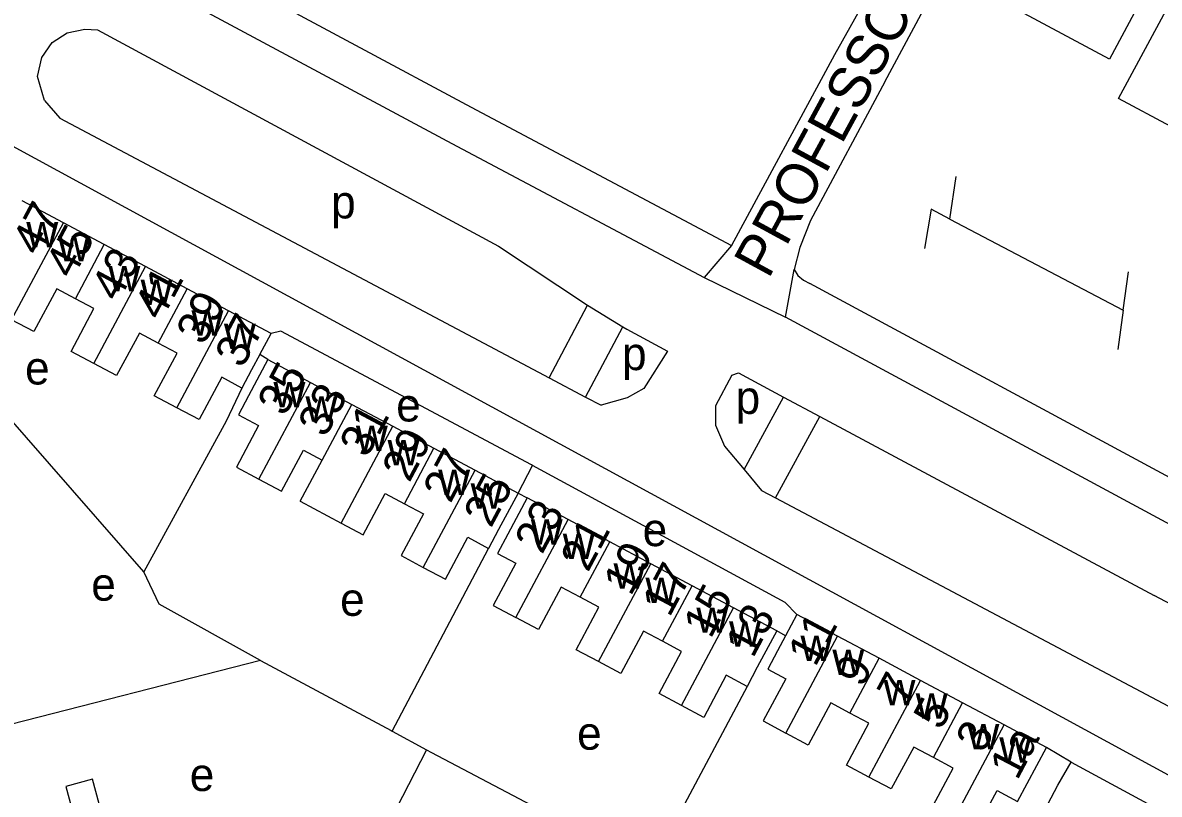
# Model space of a CAD drawing. Extents: x 159261 to 160849, y 382514 to 384534.
# Drawn here: x 159830 to 159967.8, y 383889.9 to 383983.5 of the extents above; entities that cross this region are included whole.
import ezdxf

# ---------------------------------------------------------------- set-up
doc = ezdxf.new("R2010")
doc.units = 0
for name, color, linetype in [('BLT_Basislijn', 7, 'Continuous'), ('BLT_Bebouwing', 7, 'Continuous'), ('BLT_Centroide', 7, 'Continuous'), ('BLT_Huisnummer', 7, 'Continuous'), ('BLT_Huisnummer_ tussenligend', 7, 'Continuous'), ('BLT_Onderverdeling_panden', 7, 'Continuous'), ('BLT_Straatnaam', 7, 'Continuous'), ('BLT_Vlakafsluiter', 7, 'Continuous')]:
    doc.layers.add(name, color=color, linetype=linetype)

msp = doc.modelspace()

# ---------------------------------------------------------------- linework, layer by layer
at = {"layer": 'BLT_Basislijn'}
for p, q in [((159839.08, 383982.65), (159887.72, 383956.4)), ((159934.58, 383976.36), (159925.54, 383959.53)), ((159832.65, 383974.09), (159834.49, 383971.94)), ((159834.49, 383971.94), (159893.84, 383940.44)), ((159942.45, 383959.68), (159943.21, 383964.85)), ((159942.45, 383959.68), (159963.45, 383948.63)), ((159887.72, 383956.4), (159898.51, 383949.24)), ((159915.98, 383956.49), (159912.64, 383952.6)), ((159963.45, 383948.63), (159964.13, 383953.27)), ((159893.84, 383940.44), (159898.51, 383949.24)), ((159963.45, 383948.63), (159962.81, 383943.87)), ((159898.25, 383938.09), (159902.78, 383946.63)), ((159908.2, 383943.68), (159905.32, 383939.15)), ((159859.73, 383942.63), (159858.76, 383943.25)), ((159916.01, 383940.76), (159914.02, 383937.04)), ((159893.84, 383940.44), (159898.25, 383938.09)), ((159898.25, 383938.09), (159900.14, 383937.09)), ((159917.49, 383929.28), (159922.27, 383938.09)), ((159921.32, 383925.85), (159926.68, 383935.73)), ((159890.08, 383926.42), (159891.85, 383929.8)), ((159890.08, 383926.42), (159891.19, 383925.88)), ((159919.59, 383926.76), (159921.32, 383925.85)), ((159921.32, 383925.85), (160059.63, 383852.41)), ((159874.82, 383897.54), (159886.5, 383919.73)), ((159970.74, 383912.14), (159967.23, 383914.01)), ((159922.53, 383909.11), (159921.45, 383909.72)), ((159858.86, 383906.11), (159823.8, 383897.17)), ((159917.85, 383902.98), (159908.67, 383885.71)), ((159874.82, 383897.54), (159878.99, 383895.29)), ((159878.99, 383895.29), (159867.87, 383873.72)), ((159957.15, 383893.79), (159954.15, 383895.56)), ((159957.15, 383893.79), (159967.4, 383888.25))]:
    msp.add_line(p, q, dxfattribs=at)
for points in [[(159957.87, 384042.43), (159958.71, 384041.58), (159959.45, 384040.29), (159959.85, 384038.79), (159959.81, 384037.11), (159936.09, 383993.31), (159928.44, 383979.64)], [(159934.58, 383976.36), (159962.75, 384028.88), (159963.83, 384030.2), (159964.72, 384031.01), (159965.91, 384031.42), (159967.49, 384031.39), (159970.07, 384030.28)], [(159809.86, 384007.63), (159882.05, 383968.86), (159912.64, 383952.6)], [(159842.32, 383995.87), (159884.41, 383973.27), (159915.98, 383956.49)], [(159832.65, 383974.09), (159831.79, 383976.99), (159832.31, 383979.3), (159833.59, 383981.1), (159835.38, 383982.3), (159837.52, 383982.72), (159839.08, 383982.65)], [(159928.44, 383979.64), (159915.98, 383956.49)], [(159823.19, 383971.58), (160049.97, 383848.1), (160067.5, 383838.6), (160083.66, 383829.43)], [(159942.45, 383959.68), (159940.17, 383960.89), (159939.39, 383956.12)], [(159925.54, 383959.53), (159924.26, 383956.25), (159923.58, 383953.58)], [(159922.51, 383947.79), (159923.58, 383953.58)], [(159923.58, 383953.58), (159924.02, 383952.85), (159924.7, 383952.29), (159925.48, 383951.86)], [(159971.17, 383927.2), (159925.48, 383951.86)], [(159898.51, 383949.24), (159902.78, 383946.63)], [(160121.72, 383847.78), (160116.87, 383847.25), (160111.62, 383847.44), (160105.79, 383849.21), (159987.63, 383912.63), (159922.51, 383947.79)], [(159902.78, 383946.63), (159903.27, 383946.33), (159908.2, 383943.68)], [(159891.85, 383929.8), (159891.7, 383929.88), (159861.3, 383946.09), (159860.12, 383945.8)], [(159844.68, 383916.88), (159821.76, 383943.08), (159811.97, 383941.18)], [(159916.01, 383940.76), (159916.8, 383941.03), (159922.27, 383938.09)], [(159856.59, 383939.19), (159854.69, 383935.16), (159844.68, 383916.88)], [(159905.32, 383939.15), (159903.32, 383937.99), (159900.14, 383937.09)], [(159922.27, 383938.09), (159926.68, 383935.73)], [(159914.02, 383937.04), (159914.02, 383934.68), (159915.11, 383932.14), (159917.49, 383929.28)], [(159926.68, 383935.73), (159967.23, 383914.01)], [(159923.91, 383911.71), (159922.47, 383913.16), (159891.85, 383929.8)], [(159917.49, 383929.28), (159919.59, 383926.76)], [(159858.86, 383906.11), (159846.57, 383912.97), (159844.68, 383916.88)], [(159858.86, 383906.11), (159874.7, 383897.61), (159874.82, 383897.54)], [(159878.99, 383895.29), (159879.59, 383894.97), (159906.08, 383881)], [(159943.21, 383867.55), (159955.54, 383890.99), (159957.15, 383893.79)]]:
    msp.add_lwpolyline(points, dxfattribs=at)
at = {"layer": 'BLT_Bebouwing'}
for p, q in [((159834.94, 383959.25), (159829.95, 383961.91)), ((159839.9, 383956.6), (159834.94, 383959.25)), ((159844.91, 383953.92), (159839.9, 383956.6)), ((159849.95, 383951.23), (159844.91, 383953.92)), ((159854.97, 383948.55), (159849.95, 383951.23)), ((159860.12, 383945.8), (159854.97, 383948.55)), ((159858.76, 383943.25), (159860.12, 383945.8)), ((159859.73, 383942.63), (159864.92, 383939.86)), ((159864.92, 383939.86), (159869.93, 383937.18)), ((159869.93, 383937.18), (159874.88, 383934.54)), ((159874.88, 383934.54), (159879.88, 383931.87)), ((159879.88, 383931.87), (159884.88, 383929.2)), ((159863.66, 383925.44), (159866.34, 383930.42)), ((159884.88, 383929.2), (159890.08, 383926.42)), ((159896.17, 383923.22), (159891.19, 383925.88)), ((159901.19, 383920.53), (159896.17, 383923.22)), ((159906.19, 383917.86), (159901.19, 383920.53)), ((159911.21, 383915.18), (159906.19, 383917.86)), ((159916.22, 383912.51), (159911.21, 383915.18)), ((159921.45, 383909.72), (159916.22, 383912.51)), ((159923.91, 383911.71), (159922.53, 383909.11)), ((159928.83, 383909.08), (159923.91, 383911.71)), ((159933.87, 383906.39), (159928.83, 383909.08)), ((159938.89, 383903.71), (159933.87, 383906.39)), ((159943.99, 383900.98), (159938.89, 383903.71)), ((159949.02, 383898.3), (159943.99, 383900.98)), ((159954.15, 383895.56), (159949.02, 383898.3)), ((159950.65, 383889.03), (159954.15, 383895.56))]:
    msp.add_line(p, q, dxfattribs=at)
for points in [[(159970.51, 383995.35), (159961.81, 383979.1), (159951.48, 383984.63), (159953.26, 383987.93), (159946.71, 383991.49), (159951.27, 384000), (159959.26, 384014.93), (159969.46, 384009.45), (159967.72, 384006.18), (159974.4, 384002.61), (159973, 384000)], [(159836.39, 383950.03), (159834.13, 383951.23), (159831.35, 383946.04), (159828.65, 383947.48)], [(159838.63, 383942.17), (159835.88, 383943.64), (159838.64, 383948.82), (159836.39, 383950.03)], [(159846.43, 383944.64), (159844.15, 383945.86), (159841.39, 383940.7), (159838.63, 383942.17)], [(159848.69, 383936.8), (159845.96, 383938.26), (159848.72, 383943.42), (159846.43, 383944.64)], [(159859.73, 383942.63), (159857.37, 383938.22), (159856.16, 383935.95), (159858.61, 383934.65), (159855.92, 383929.6), (159858.66, 383928.14)], [(159858.76, 383943.25), (159857.77, 383941.39), (159856.59, 383939.19)], [(159856.59, 383939.19), (159854.17, 383940.49), (159851.42, 383935.35), (159848.69, 383936.8)], [(159858.66, 383928.14), (159861.4, 383926.68), (159864.05, 383931.64), (159866.34, 383930.42)], [(159868.61, 383922.8), (159871.28, 383921.37), (159873.96, 383926.39), (159876.29, 383925.15)], [(159890.08, 383926.42), (159887.72, 383922.01), (159886.5, 383919.73)], [(159891.19, 383925.88), (159888.83, 383921.47), (159887.58, 383919.11), (159889.81, 383917.92), (159887.08, 383912.8), (159889.82, 383911.34)], [(159863.66, 383925.44), (159868.61, 383922.8)], [(159876.29, 383925.15), (159878.61, 383923.91), (159875.91, 383918.85), (159878.59, 383917.42)], [(159878.59, 383917.42), (159881.27, 383915.99), (159883.99, 383921.07), (159886.5, 383919.73)], [(159897.6, 383913.8), (159895.31, 383915.02), (159892.56, 383909.88), (159889.82, 383911.34)], [(159899.85, 383905.98), (159897.13, 383907.43), (159899.88, 383912.58), (159897.6, 383913.8)], [(159907.61, 383908.45), (159905.31, 383909.68), (159902.56, 383904.53), (159899.85, 383905.98)], [(159921.45, 383909.72), (159919.09, 383905.31), (159917.85, 383902.98)], [(159922.53, 383909.11), (159921.56, 383907.3), (159920.36, 383905.05), (159922.55, 383903.89), (159919.82, 383898.78), (159922.55, 383897.32)], [(159909.89, 383900.66), (159907.18, 383902.11), (159909.91, 383907.22), (159907.61, 383908.45)], [(159917.85, 383902.98), (159915.33, 383904.33), (159912.6, 383899.21), (159909.89, 383900.66)], [(159930.31, 383899.74), (159928, 383900.97), (159925.28, 383895.86), (159922.55, 383897.32)], [(159932.63, 383891.98), (159929.91, 383893.43), (159932.62, 383898.5), (159930.31, 383899.74)], [(159940.45, 383894.35), (159938.06, 383895.62), (159935.34, 383890.53), (159932.63, 383891.98)], [(159942.77, 383886.59), (159940.99, 383887.53), (159940.13, 383888), (159942.84, 383893.07), (159940.45, 383894.35)], [(159842.49, 383876.85), (159841.19, 383881.68), (159838.48, 383891.73), (159835.24, 383890.85), (159837.02, 383884.22), (159834.55, 383883.55)], [(159942.77, 383886.59), (159945.4, 383885.18), (159948.17, 383890.36), (159950.65, 383889.03)]]:
    msp.add_lwpolyline(points, dxfattribs=at)
msp.add_lwpolyline([(159962.92, 383974.33), (159971.95, 383991.17), (159984.61, 383984.38), (159975.58, 383967.54)], close=True, dxfattribs=at)
at = {"layer": 'BLT_Onderverdeling_panden'}
for p, q in [((159828.65, 383947.48), (159834.94, 383959.25)), ((159836.39, 383950.03), (159839.9, 383956.6)), ((159838.63, 383942.17), (159844.91, 383953.92)), ((159846.43, 383944.64), (159849.95, 383951.23)), ((159848.69, 383936.8), (159854.97, 383948.55)), ((159858.66, 383928.14), (159864.92, 383939.86)), ((159866.34, 383930.42), (159869.93, 383937.18)), ((159868.61, 383922.8), (159874.88, 383934.54)), ((159876.29, 383925.15), (159879.88, 383931.87)), ((159878.59, 383917.42), (159884.88, 383929.2)), ((159889.82, 383911.34), (159896.17, 383923.22)), ((159897.6, 383913.8), (159901.19, 383920.53)), ((159899.85, 383905.98), (159906.19, 383917.86)), ((159907.61, 383908.45), (159911.21, 383915.18)), ((159909.89, 383900.66), (159916.22, 383912.51)), ((159922.55, 383897.32), (159928.83, 383909.08)), ((159930.31, 383899.74), (159933.87, 383906.39)), ((159932.63, 383891.98), (159938.89, 383903.71)), ((159940.45, 383894.35), (159943.99, 383900.98)), ((159942.77, 383886.59), (159949.02, 383898.3))]:
    msp.add_line(p, q, dxfattribs=at)
at = {"layer": 'BLT_Vlakafsluiter'}
msp.add_line((159912.64, 383952.6), (159922.51, 383947.79), dxfattribs=at)

# ---------------------------------------------------------------- texts
at = {"layer": 'BLT_Centroide'}
for s, p in [('p', (159867.41, 383959.77)), ('w', (159830.44, 383956.25)), ('w', (159834.28, 383954.58)), ('w', (159840.39, 383950.91)), ('w', (159844.3, 383949.27)), ('w', (159850.47, 383945.55)), ('w', (159854.41, 383943.94)), ('p', (159902.69, 383941.36)), ('e', (159830.29, 383939.62)), ('w', (159860.42, 383936.84)), ('w', (159864.3, 383935.09)), ('e', (159875.3, 383935.13)), ('p', (159916.47, 383936.05)), ('w', (159870.41, 383931.55)), ('w', (159874.25, 383929.8)), ('w', (159880.39, 383926.2)), ('w', (159884.33, 383924.53)), ('w', (159891.62, 383920.19)), ('e', (159905.19, 383920)), ('w', (159895.5, 383918.45)), ('w', (159901.66, 383914.83)), ('e', (159838.32, 383913.38)), ('w', (159905.53, 383913.09)), ('e', (159868.5, 383911.54)), ('w', (159911.7, 383909.48)), ('w', (159915.67, 383907.81)), ('w', (159924.33, 383906.08)), ('w', (159928.2, 383904.38)), ('w', (159934.41, 383900.7)), ('w', (159938.31, 383899.06)), ('e', (159897.24, 383895.3)), ('w', (159944.58, 383895.33)), ('w', (159948.45, 383893.72)), ('e', (159850.26, 383890.28))]:
    msp.add_text(s, height=4, dxfattribs=at).set_placement(p)
at = {"layer": 'BLT_Huisnummer'}
for s, rotation, p in [('47', 61.8841, (159831.99, 383955.05)), ('43', 61.8967, (159841.6, 383949.5)), ('37', 61.9018, (159856.64, 383941.46)), ('33', 61.8971, (159866.71, 383933.05)), ('29', 61.8882, (159876.89, 383927.61)), ('17', 61.8939, (159908.44, 383911.25)), ('13', 61.9023, (159918.56, 383906.29)), ('7', 61.8957, (159936.95, 383900.57)), ('1a', 62.2491, (159950.62, 383891.47))]:
    msp.add_text(s, height=4, rotation=rotation, dxfattribs=at).set_placement(p)
at = {"layer": 'BLT_Huisnummer_ tussenligend'}
for s, rotation, p in [('45', 61.8967, (159836.04, 383952.28)), ('41', 61.9018, (159846.81, 383947.22)), ('39', 61.9018, (159851.94, 383944.25)), ('35', 61.8971, (159861.79, 383935.61)), ('31', 61.8882, (159871.75, 383930.58)), ('27', 61.894, (159881.87, 383925.08)), ('25', 61.894, (159886.79, 383922.1)), ('23', 61.894, (159892.99, 383918.89)), ('21', 61.894, (159898.55, 383916.72)), ('19', 61.8939, (159903.74, 383913.82)), ('15', 61.9023, (159913.43, 383908.65)), ('11', 61.8957, (159926.12, 383905.23)), ('9', 61.8957, (159931.82, 383902.72)), ('5', 62.2491, (159941.38, 383897.55)), ('3', 62.2491, (159946.51, 383894.76))]:
    msp.add_text(s, height=4, rotation=rotation, dxfattribs=at).set_placement(p)
at = {"layer": 'BLT_Straatnaam'}
msp.add_text('PROFESSOR HOROWITZSTRAAT', height=5, rotation=61.4651, dxfattribs=at).set_placement((159920.45, 383952.32))

doc.saveas('drawing.dxf')
